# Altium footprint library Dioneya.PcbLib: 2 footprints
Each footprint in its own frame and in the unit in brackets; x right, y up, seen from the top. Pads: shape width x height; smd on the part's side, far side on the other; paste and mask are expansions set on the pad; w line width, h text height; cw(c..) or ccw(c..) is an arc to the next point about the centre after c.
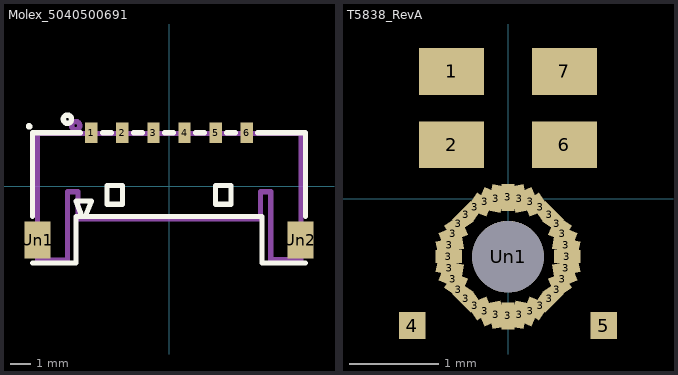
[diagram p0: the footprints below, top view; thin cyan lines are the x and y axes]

## Molex_5040500691 [mm]
pads (8):
  rect 0.6x1 smd: 1(-3.75,2.59) 2(-2.25,2.59) 3(-0.75,2.59) 4(0.75,2.59) 5(2.25,2.59) 6(3.75,2.59)
  rect 1.25x1.8 smd: Un1(-6.35,-2.59) Un2(6.35,-2.59)
F.SilkS:
  circle w0.254: c-6.76,2.9 r0.03
  circle w0.254: c-4.91,3.25 r0.2
  lines w0.254: -6.6,-3.7 -4.5,-3.7 -4.5,-1.45 4.5,-1.45 4.5,-3.7 6.6,-3.7 ; -6.6,-1.45 -6.6,2.59 -4.28,2.59 ; -4.2,-1.45 -4.5,-0.71 -3.75,-0.71 -4.05,-1.45 ; -3.22,2.59 -2.78,2.59 ; -1.72,2.59 -1.28,2.59 ; -0.22,2.59 0.22,2.59 ; 1.28,2.59 1.72,2.59 ; 2.78,2.59 3.22,2.59 ; 4.28,2.59 6.6,2.59 6.6,-1.45 ; -3,-0.86 -3,0.04 -2.25,0.04 -2.25,-0.86 -3,-0.86 ; 2.25,-0.86 2.25,0.04 3,0.04 3,-0.86 2.25,-0.86
F.Fab:
  text "'.Designator'" at -1.439,-0.398 h1
F.CrtYd:
  lines w0.254: -6.36,-3.56 -6.36,2.56 6.38,2.56 6.38,-3.54 4.92,-3.54 4.92,-0.26 4.42,-0.26 4.42,-1.56 -4.4,-1.56 -4.4,-0.26 -4.9,-0.26 -4.9,-3.54 -6.36,-3.56
Cmts.User:
  circle w0.254: c-4.51,2.94 r0.2

## T5838_RevA [mm]
pads (39):
  rect 0.725x0.522 smd: 1(-0.63,1.42) 2(-0.63,0.6) 6(0.63,0.6) 7(0.63,1.42)
  rect 0.3x0.146 smd: 3(-0.663,-0.65) 3(0.663,-0.65)
  rect 0.146x0.3 smd rot 78.75: 3(-0.65,-0.779) 3(0.65,-0.521)
  rect 0.146x0.3 smd rot 101.25: 3(-0.65,-0.521) 3(0.65,-0.779)
  rect 0.146x0.3 smd rot 67.5: 3(-0.612,-0.904) 3(0.612,-0.396)
  rect 0.146x0.3 smd rot 112.5: 3(-0.612,-0.396) 3(0.612,-0.904)
  rect 0.146x0.3 smd rot 56.25: 3(-0.551,-1.018) 3(0.551,-0.282)
  rect 0.146x0.3 smd rot 123.75: 3(-0.551,-0.282) 3(0.551,-1.018)
  rect 0.146x0.3 smd rot 45: 3(-0.468,-1.118) 3(0.468,-0.182)
  rect 0.146x0.3 smd rot 135: 3(-0.468,-0.182) 3(0.468,-1.118)
  rect 0.146x0.3 smd rot 33.75: 3(-0.368,-1.201) 3(0.368,-0.099)
  rect 0.146x0.3 smd rot 146.25: 3(-0.368,-0.099) 3(0.368,-1.201)
  rect 0.146x0.3 smd rot 22.5: 3(-0.254,-1.262) 3(0.254,-0.038)
  rect 0.146x0.3 smd rot 157.5: 3(-0.254,-0.038) 3(0.254,-1.262)
  rect 0.146x0.3 smd rot 11.25: 3(-0.129,-1.3) 3(0.129,0)
  rect 0.146x0.3 smd rot 168.75: 3(-0.129,0) 3(0.129,-1.3)
  rect 0.146x0.3 smd: 3(0,-1.312) 3(0,0.013)
  rect 0.3x0.3 smd: 4(-1.07,-1.42) 5(1.07,-1.42)
  round 0.8 hole 0.8: Un1(0,-0.65)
